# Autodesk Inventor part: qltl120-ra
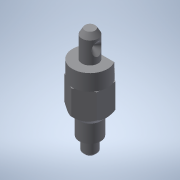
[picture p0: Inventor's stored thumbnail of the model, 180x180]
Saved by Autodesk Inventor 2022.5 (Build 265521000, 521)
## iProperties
Created: 2016-12
Part Number: qltl120-ra
Material: 一般
Document SubType Name: Modeling
Designer: imaocorp
Density: 1 g/cm^3
Appearance: 既定
Author: imaocorp
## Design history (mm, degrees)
node "qltl120-ra.x_t1"
node "qltl120-ra"
node "Base1"
